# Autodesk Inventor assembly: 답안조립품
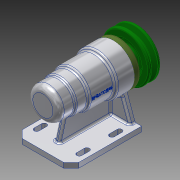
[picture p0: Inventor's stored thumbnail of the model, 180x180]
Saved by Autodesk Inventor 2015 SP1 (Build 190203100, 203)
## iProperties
Created: 2017-09
Part Number: 답안조립품
Document SubType Name: Assembly
Designer: C04
Author: C04
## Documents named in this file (12)
- C:\Users\C04\Desktop\답안조립품.iam
- C:\Users\C04\Desktop\본체.ipt
- C:\Users\C04\Desktop\커버.ipt
- C:\Users\C04\Desktop\오일 실 20x35x7.ipt
- C:\Users\C04\Desktop\베어링 6004.ipt
- C:\Users\C04\Desktop\축.ipt
- C:\Users\C04\Desktop\키 5 x 5 x 16.ipt
- C:\Users\C04\Desktop\V벨트풀리.ipt
- C:\Users\C04\Desktop\어댑터슬리브.ipt
- C:\Users\C04\Desktop\베어링 51202.ipt
- C:\Users\C04\Desktop\볼트 M4 x 12.ipt
- C:\Users\C04\Desktop\멈춤나사 M3x8.ipt
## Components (1 placed, 1 different names)
1. V벨트풀리:1 — 각도:1
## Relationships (1: Angle 1)
- 각도:1 [Angle]: V벨트풀리:1
